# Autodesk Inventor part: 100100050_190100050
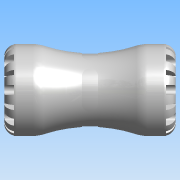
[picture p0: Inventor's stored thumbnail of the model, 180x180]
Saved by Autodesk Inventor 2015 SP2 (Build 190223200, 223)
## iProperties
Created: 2016-12
Part Number: 100100050_190100050
Material: PVC-Piping
Description: PLASSON COUPLER 50X50 SERIES 1
Document SubType Name: Modeling
Designer: KIM
Mass: 95.2094 g
Surface Area: 200.83 cm^2
Volume: 68.0067 cm^3
Density: 1.4 g/cm^3
Appearance: Smooth - White
ILogicFactory: False
Author: KIM
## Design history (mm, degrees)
derived "1001.ipt"
feature "Solid1::1001.ipt"
tag "TaggingFeature1"
body "Solid1"
other parameters: "d2" = 78, "d4" = 4.16667, "d11" = 9, "d13" = 9, "d14" = 0, "d16" = 360 deg, "d18" = 8 deg, "d19" = 1, "d20" = 8 deg, "d21" = 1, "d23" = 0, "d25" = 360 deg, "d27" = 34, "d28" = 12.5, "d29" = 15, "d30" = 15, "d31" = 0, "d33" = 0, "d37" = 31.6, "d38" = 0.85, "d43" = 6.25, "d45" = 31.6, "d46" = 68, "d47" = 85, "d48" = 158, "d50" = 360 deg, "d54" = 0.513, "E_" = 85, "H_" = 158, "l_" = 78, "d12" = 62.5, "d42" = 85, "d52" = 11.25
